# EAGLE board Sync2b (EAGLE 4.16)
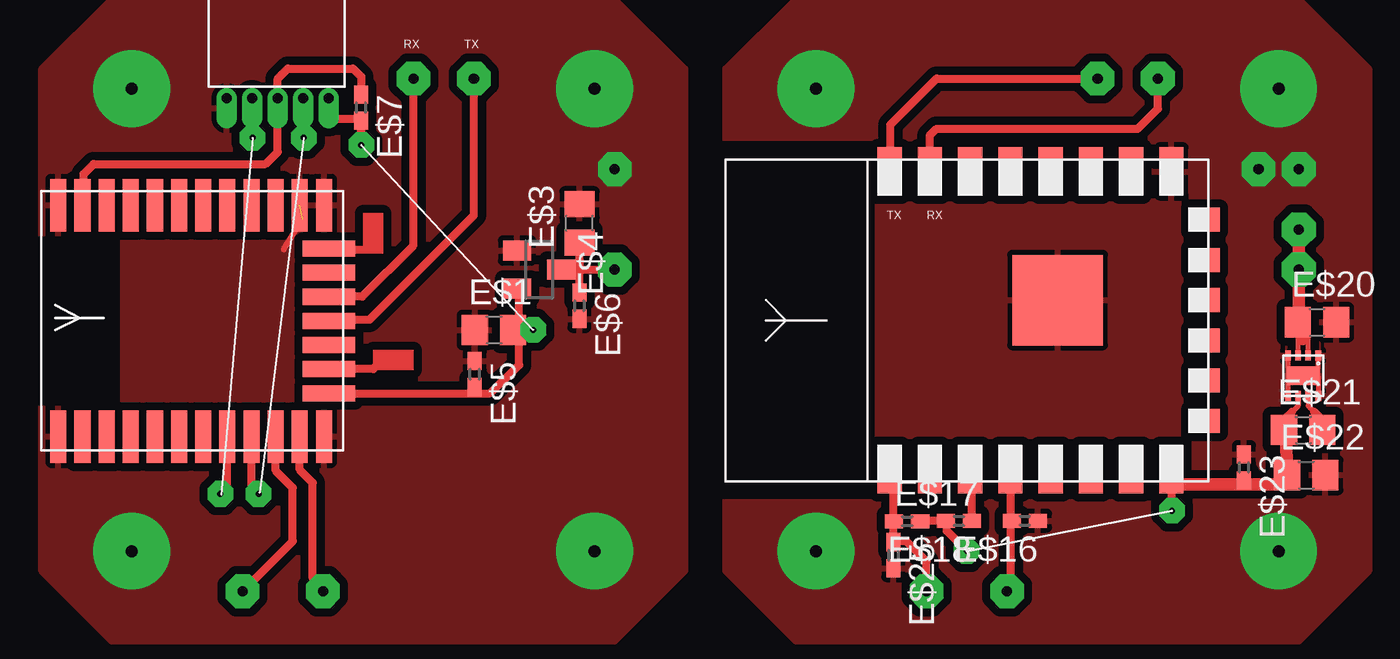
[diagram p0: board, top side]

No outline drawn. Coordinates in mm, seen from the top.
Copper layers (1*16): Top 0.035mm / dielectric 1.5mm / Bottom 0.035mm
Design rules "default": minimum track width 10mil, minimum drill 24mil, track to track 8mil, track to pad 8mil, pad to pad 8mil, via to via 8mil, smd to smd 8mil, copper to edge 40mil, drill to drill 8mil, minimum pad ring 10mil, minimum via ring 8mil, stop-mask expansion 4mil, vias tented up to drill 0mil, thermal gap 10mil
tRestrict: area 34,7.5 to 41,24.5

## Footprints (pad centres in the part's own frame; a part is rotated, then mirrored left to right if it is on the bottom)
C0805 = smd 1.3 x 1.5: 1 -0.95,0; 2 0.95,0
BGM13P = smd 2.6 x 0.8: 1 0.7,14.15; 2 0.7,12.95; 3 0.7,11.75; 4 0.7,10.55; 5 0.7,9.35; 6 0.7,8.15; 7 0.7,6.95; 8 0.7,5.75; 9 0.7,4.55; 10 0.7,3.35; 11 0.7,2.15; 12 0.7,0.95; 20 12.2,0.95; 21 12.2,2.15; 22 12.2,3.35; 23 12.2,4.55; 24 12.2,5.75; 25 12.2,6.95; 26 12.2,8.15; 27 12.2,9.35; 28 12.2,10.55; 29 12.2,11.75; 30 12.2,12.95; 31 12.2,14.15 | smd 0.8 x 2.6: 13 2.85,0.7; 14 4.05,0.7; 15 5.25,0.7; 16 6.45,0.7; 17 7.65,0.7; 18 8.85,0.7; 19 10.05,0.7
SOT23 = smd 1 x 1.4: 1 -0.95,-1.1; 2 0.95,-1.1; 3 0,1.1
R0402 = smd 0.9 x 0.7: 1 -0.65,0; 2 0.65,0
HEADER5S_R = drill 0.5 offset: P$1 -2.54,-1.27; P$2 -1.27,-1.27; P$3 0,-1.27; P$4 1.27,-1.27; P$5 2.54,-1.27
WIZ360 = smd 2.4 x 1.2: 1 0.6,16; 2 0.6,14; 3 0.6,12; 4 0.6,10; 5 0.6,8; 6 0.6,6; 7 0.6,4; 8 0.6,2; 15 15.4,2; 16 15.4,4; 17 15.4,6; 18 15.4,8; 19 15.4,10; 20 15.4,12; 21 15.4,14; 22 15.4,16 | smd 1.2 x 1.5: 9 3,0.35; 10 5,0.35; 11 7,0.35; 12 9,0.35; 13 11,0.35; 14 13,0.35 | smd 4.5 x 4.5: GND 9,7.65
WSON8 = smd 0.28 x 0.5: 1 -1,-1; 2 -0.5,-1; 3 0,-1; 4 0.5,-1; 5 0.5,1; 6 0,1; 7 -0.5,1; 8 -1,1 | smd 1.6 x 0.9: EP -0.25,0

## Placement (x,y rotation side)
E$1  [C0805]  22.5,15.5 0 top
E$2  [BGM13P]  15,9.5 90 top
E$3  [C0805]  26.75,20.8 90 top
E$4  [SOT23]  24.75,18.5 270 top
E$5  [R0402]  21.55,13.3 270 top
E$6  [R0402]  26.75,16.7 270 top
E$7  [R0402]  15.89,26.55 270 top
E$8  [HEADER5S_R]  11.75,28.3 0 top
E$15  [WIZ360]  58.16,7.98 90 top
E$16  [R0402]  48.88,6.01 180 top
E$17  [R0402]  43.03,5.99 0 top
E$18  [R0402]  45.6,6 180 top
E$19  [WSON8]  62.47,13.22 180 top
E$20  [C0805]  63.41,15.88 0 top
E$21  [C0805]  62.72,10.52 0 top
E$22  [C0805]  62.87,8.28 0 top
E$23  [R0402]  59.77,8.66 270 top
E$25  [R0402]  42.34,4.3 270 top

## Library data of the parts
E$1 E$3-E$7 E$16-E$18 E$20-E$23 E$25 = ref-packages
E$2 = silabs
E$8 = sb
E$15 = esp8266
E$19 = texas

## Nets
GND: E$1.1 E$2.1 E$2.12 E$2.20 E$2.21 E$2.31 E$3.2 E$4.1 E$5.1 E$6.2 E$8.P$1
GND1: E$15.15 E$15.GND E$16.1 E$19.1 E$19.4 E$19.5 E$19.8 E$19.EP E$20.2 E$22.2 E$23.1 E$25.2
S$51: E$19.7
S$52: E$19.6
S$53: E$19.2
S$54: E$19.3

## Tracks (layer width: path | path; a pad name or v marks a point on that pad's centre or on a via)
GND  (via drill 0.5 pad 1.68, 0.6 pad 3.81)  (1 unrouted)
  Top 0.305: 12.05,19.5 13,21
  other vias: 4.5,4.5 27.5,4.5 4.5,27.5 27.5,27.5 28.5,23.5
  pour Top (isolate 0.406): 0,28.5 3.5,32 28.5,32 32,28.5 32,3.5 28.5,0 3.5,0 0,3.5
GND1  (via drill 0.5 pad 1.68, 0.6 pad 3.81)
  Top 0.254: 63.47,13.22 E$19.1 | 63.47,13.22 E$19.8 | E$19.5 61.97,13.22 | 61.97,13.22 63.47,13.22 | 61.97,13.22 E$19.4
  other vias: 61.5,27.5 61.5,4.5 38.5,27.5 38.5,4.5 62.5,23.5 60.5,23.5
  pour Top (isolate 0.406): 34,28.5 37.5,32 62.5,32 66,28.5 66,3.5 62.5,0 37.5,0 34,3.5
S$1
  Top 0.406: 15.9,24.7 15.9,26 14.4,26
S$2  (via drill 0.3 pad 1.27)
  other vias: 8.9,7.35
S$3
  Top 0.406: 15.35,12.35 22.3,12.35 23.75,13.75 23.75,17.6
S$4  (via drill 0.3 pad 1.27)
  other vias: 13.05,25.05
S$5  (via drill 0.3 pad 1.27)
  other vias: 10.5,25.05
S$6
  Top 0.406: 15.5,13.55 16.5,13.55 17,14.05
S$7  (via drill 0.3 pad 1.27)
  other vias: 10.8,7.35
S$8
  Top 0.406: 11.75,26 11.75,24.35 11.15,23.75 2.6,23.75 2.1,23.25 2.1,22.6
S$9
  Top 0.406: 46.25,6.05 46.25,8.05
S$10
  Top 0.406: 42.35,5.15 42.35,8
S$11
  Top 0.406: 11.75,27 11.75,28 12.25,28.5 15.5,28.5 15.9,28.1 15.9,27.55
S$12
  Top 0.406: 56.2,6.5 56.2,7.5
S$13  (via drill 0.3 pad 1.27)  (1 unrouted)
  other vias: 45.99,4.51 56.2,6.51
S$14  (via drill 0.5 pad 1.68)
  Top 0.406: 12.85,9.55 12.85,8.55 13.5,7.9 13.5,3.15 v14,2.5
S$15
  Top 0.406: 15.45,17.15 15.95,17.15 18.5,19.7 18.5,28
S$16  (via drill 0.5 pad 1.68)
  Top 0.406: 26.75,18.5 26.25,18.5 | 26.75,18.5 v28.5,18.5 | 26.75,19 26.75,18.5 | 26.75,19 26.75,20 | 26.75,17.5 26.75,19
S$17  (via drill 0.5 pad 1.68)
  Top 0.406: 42.2,24.35 42.2,25.7 44.5,28 v52.5,28
S$18  (via drill 0.5 pad 1.68)
  Top 0.406: 44.15,24.15 44.15,25.15 44.5,25.5 54.5,25.5 55.5,26.5 v55.5,28
S$19  (via drill 0.3 pad 1.27)
  other vias: 24.45,15.5
S$20  (via drill 0.5 pad 1.68)
  other vias: 18.5,28
S$21  (via drill 0.5 pad 1.68)
  Top 0.61: 62.7,15.05 62.7,16.3 62.5,16.3 v62.5,18.5 v62.5,20.5
S$22  (via drill 0.3 pad 1.27)
  other vias: 15.9,24.7
S$23
  Top 0.406: 48.2,2.5 48.2,8
S$24  (via drill 0.5 pad 1.68)
  Top 0.406: v21.5,28 21.5,21.2 16.3,16 15.3,16
S$25
  Top 0.406: 15.9,24.65 15.9,26.15
S$26  (via drill 0.5 pad 1.68)
  Top 0.406: 11.65,9.5 11.65,8.5 12.5,7.65 12.5,5 v10,2.5
S$27  (via drill 0.5 pad 1.68)
  Top 0.406: 42.5,5 43,5 44,4 v44,2.5
S$28  (via drill 0.5 pad 1.68)
  other vias: 48,2.5
S$29
  Top 0.406: 10.45,7.5 10.45,9.5
S$30
  Top 0.406: 9.25,7.45 9.25,9.45
S$31
  Top 0.406: 14.5,19.5 16.5,19.5
S$51
  Top 0.254: E$19.7 62.97,11.73 63.27,11.43
  Top 0.406: 63.27,11.43 63.63,11.07 63.63,10.22
S$52
  Top 0.254: E$19.6 62.47,11.73 62.17,11.43
  Top 0.406: 62.17,11.43 61.81,11.07 61.81,10.22
S$53
  Top 0.254: E$19.2 62.97,15.47
S$54
  Top 0.254: E$19.3 62.47,15.46
S$55
  Top 0.61: 61.88,10.57 61.9,8.1 61.95,7.82 59.48,7.82 56.12,7.83
S$64
  Top 0.406: 44,6 45,6 45,5.5 46,4.5
(copper drawn outside any net)
  shapes: Top area x2

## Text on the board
tPlace: RX | TX | TX | RX
tNames: D | C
